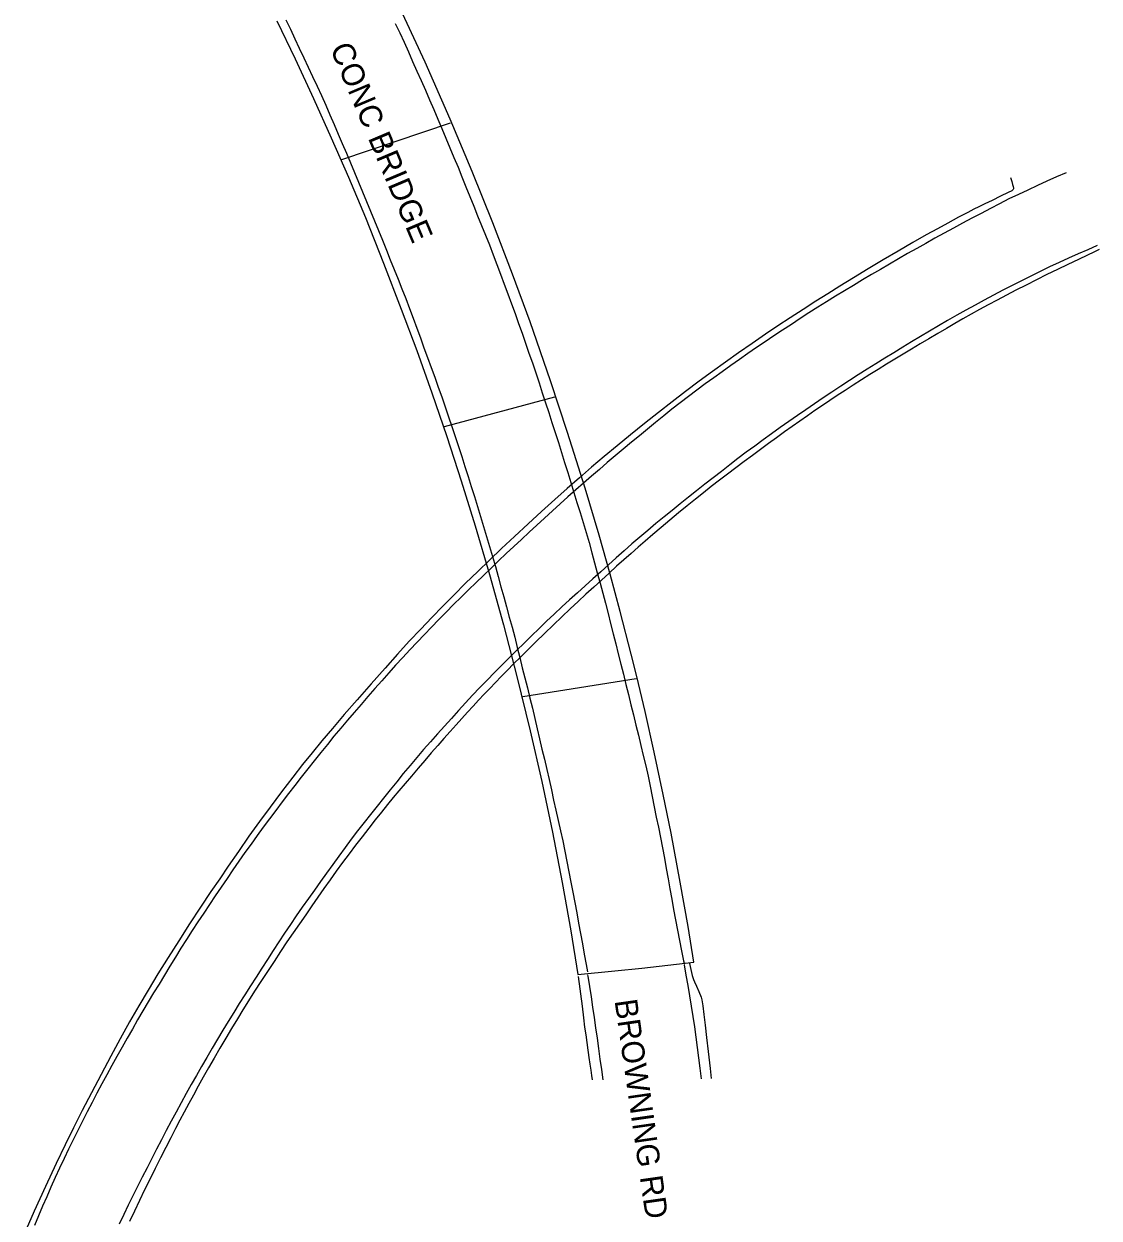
# Model space of a CAD drawing. Extents: x 1948091 to 1975253, y 787267 to 823306.
# Drawn here: x 1967398.7 to 1967655.4, y 801796.8 to 802082 of the extents above; entities that cross this region are included whole.
import ezdxf

# ---------------------------------------------------------------- set-up
doc = ezdxf.new("R2010")
doc.units = 0
for name, color, linetype in [('RD_EX_Bridge', 7, 'Continuous'), ('RD_EX_Bridge_Seam', 7, 'Continuous'), ('RD_EX_Pavement_Markings', 7, 'Continuous'), ('RD_EX_Road', 7, 'Continuous'), ('RD_TX_RoadID', 7, 'Continuous')]:
    doc.layers.add(name, color=color, linetype=linetype)

msp = doc.modelspace()

# ---------------------------------------------------------------- linework, layer by layer
at = {"layer": 'RD_EX_Bridge'}
msp.add_lwpolyline([(1967459.07, 802082.71), (1967463.4, 802073.66), (1967467.78, 802064.2), (1967472.05, 802054.78), (1967476.13, 802045.4), (1967480.19, 802035.73), (1967484.56, 802024.82), (1967488.77, 802013.85), (1967492.47, 802004.03), (1967496.06, 801993.91), (1967499.63, 801983.43), (1967503.05, 801972.84), (1967506.42, 801962.13), (1967509.85, 801950.49), (1967513.15, 801938.46), (1967516.35, 801926.16), (1967519.57, 801913.14), (1967522.31, 801901.06), (1967524.83, 801888.96), (1967527.19, 801876.95), (1967529.26, 801865.43), (1967530.91, 801854.95), (1967539.77, 801855.85), (1967546.2, 801856.46), (1967558.64, 801857.89), (1967557.23, 801866.47), (1967555.37, 801877.04), (1967553.19, 801888.76), (1967551.31, 801897.98), (1967549.17, 801908.09), (1967547, 801917.79), (1967545, 801926.13), (1967543.64, 801931.48), (1967540.99, 801941.68), (1967538.62, 801950.58), (1967535.98, 801959.93), (1967532.63, 801971.14), (1967528.48, 801984.44), (1967524.41, 801996.76), (1967519.52, 802010.8), (1967515.35, 802022.19), (1967510.61, 802034.48), (1967505.67, 802046.75), (1967500.42, 802059.22), (1967494.44, 802072.81), (1967487.47, 802087.95)], dxfattribs=at)
at = {"layer": 'RD_EX_Bridge_Seam'}
for p, q in [((1967474.59, 802049.57), (1967500.52, 802058.35)), ((1967499.07, 801985.84), (1967525.41, 801992.92)), ((1967517.8, 801921.35), (1967544.86, 801925.65))]:
    msp.add_line(p, q, dxfattribs=at)
at = {"layer": 'RD_EX_Pavement_Markings'}
for points in [[(1967461.21, 802082.96), (1967462.28, 802080.7), (1967463.34, 802078.44), (1967464.41, 802076.18), (1967465.48, 802073.91), (1967466.54, 802071.65), (1967467.61, 802069.39), (1967468.68, 802067.13), (1967469.74, 802064.87), (1967470.77, 802062.59), (1967471.74, 802060.29), (1967472.72, 802057.99), (1967473.7, 802055.69), (1967474.68, 802053.39), (1967475.65, 802051.09), (1967476.63, 802048.79), (1967477.61, 802046.49), (1967478.57, 802044.18), (1967479.52, 802041.87), (1967480.47, 802039.55), (1967481.42, 802037.24), (1967482.37, 802034.93), (1967483.31, 802032.62), (1967484.26, 802030.3), (1967485.21, 802027.99), (1967486.14, 802025.67), (1967487.07, 802023.35), (1967488, 802021.03), (1967488.92, 802018.71), (1967489.85, 802016.39), (1967490.73, 802014.05), (1967491.6, 802011.7), (1967492.46, 802009.35), (1967493.32, 802007.01), (1967494.18, 802004.66), (1967495.04, 802002.32), (1967495.91, 801999.97), (1967496.77, 801997.62), (1967497.61, 801995.27), (1967498.42, 801992.91), (1967499.23, 801990.54), (1967500.03, 801988.17), (1967500.84, 801985.81), (1967501.65, 801983.44), (1967502.46, 801981.08), (1967503.22, 801978.7), (1967503.97, 801976.31), (1967504.71, 801973.93), (1967505.46, 801971.54), (1967506.21, 801969.16), (1967506.95, 801966.77), (1967507.68, 801964.38), (1967508.39, 801961.98), (1967509.1, 801959.59), (1967509.81, 801957.19), (1967510.51, 801954.79), (1967511.22, 801952.39), (1967511.91, 801949.99), (1967512.57, 801947.58), (1967513.23, 801945.17), (1967513.88, 801942.76), (1967514.54, 801940.35), (1967515.2, 801937.93), (1967515.85, 801935.52), (1967516.46, 801933.1), (1967517.06, 801930.67), (1967517.66, 801928.25), (1967518.27, 801925.82), (1967518.87, 801923.4), (1967519.47, 801920.97), (1967520.08, 801918.55), (1967520.65, 801916.11), (1967521.22, 801913.68), (1967521.79, 801911.25), (1967522.35, 801908.81), (1967522.92, 801906.38), (1967523.49, 801903.94), (1967524.05, 801901.51), (1967524.59, 801899.07), (1967525.14, 801896.63), (1967525.68, 801894.19), (1967526.22, 801891.75), (1967526.77, 801889.31), (1967527.31, 801886.87), (1967527.81, 801884.42), (1967528.29, 801881.97), (1967528.76, 801879.51), (1967529.23, 801877.06), (1967529.71, 801874.61), (1967530.18, 801872.15), (1967530.65, 801869.7), (1967531.1, 801867.24), (1967531.54, 801864.78), (1967531.99, 801862.32), (1967532.43, 801859.86), (1967532.88, 801857.4), (1967533.21, 801855.59)], [(1967487.32, 802082.1), (1967488.41, 802079.85), (1967489.46, 802077.59), (1967490.47, 802075.3), (1967491.48, 802073.01), (1967492.49, 802070.73), (1967493.5, 802068.44), (1967494.51, 802066.16), (1967495.53, 802063.87), (1967496.52, 802061.58), (1967497.49, 802059.27), (1967498.45, 802056.97), (1967499.42, 802054.66), (1967500.39, 802052.35), (1967501.35, 802050.05), (1967502.32, 802047.74), (1967503.25, 802045.43), (1967504.19, 802043.11), (1967505.12, 802040.79), (1967506.06, 802038.47), (1967507, 802036.15), (1967507.93, 802033.84), (1967508.87, 802031.52), (1967509.8, 802029.2), (1967510.68, 802026.86), (1967511.55, 802024.52), (1967512.43, 802022.18), (1967513.31, 802019.84), (1967514.18, 802017.49), (1967515.06, 802015.15), (1967515.94, 802012.81), (1967516.77, 802010.46), (1967517.59, 802008.1), (1967518.41, 802005.73), (1967519.23, 802003.37), (1967520.06, 802001.01), (1967520.88, 801998.65), (1967521.67, 801996.28), (1967522.44, 801993.9), (1967523.2, 801991.53), (1967523.97, 801989.15), (1967524.74, 801986.77), (1967525.5, 801984.39), (1967526.27, 801982.01), (1967527.03, 801979.63), (1967527.77, 801977.24), (1967528.5, 801974.85), (1967529.24, 801972.46), (1967529.98, 801970.07), (1967530.71, 801967.68), (1967531.45, 801965.3), (1967532.19, 801962.91), (1967532.92, 801960.52), (1967533.63, 801958.12), (1967534.28, 801955.71), (1967534.92, 801953.29), (1967535.56, 801950.88), (1967536.21, 801948.46), (1967536.85, 801946.05), (1967537.49, 801943.63), (1967538.14, 801941.22), (1967538.75, 801938.79), (1967539.36, 801936.37), (1967539.96, 801933.95), (1967540.57, 801931.52), (1967541.18, 801929.1), (1967541.78, 801926.67), (1967542.39, 801924.25), (1967542.99, 801921.82), (1967543.58, 801919.39), (1967544.18, 801916.96), (1967544.77, 801914.54), (1967545.36, 801912.11), (1967545.95, 801909.68), (1967546.55, 801907.25), (1967547.14, 801904.82), (1967547.68, 801902.38), (1967548.17, 801899.93), (1967548.66, 801897.48), (1967549.16, 801895.03), (1967549.65, 801892.58), (1967550.14, 801890.13), (1967550.63, 801887.68), (1967551.12, 801885.23), (1967551.58, 801882.78), (1967552.02, 801880.31), (1967552.47, 801877.86), (1967552.91, 801875.4), (1967553.35, 801872.94), (1967553.79, 801870.48), (1967554.24, 801868.02), (1967554.73, 801865.57), (1967555.21, 801863.11), (1967555.69, 801860.66), (1967556.18, 801858.21), (1967556.28, 801857.72)], [(1967647.46, 802046.45), (1967645.17, 802045.45), (1967642.88, 802044.45), (1967640.62, 802043.38), (1967638.36, 802042.31), (1967636.1, 802041.25), (1967633.84, 802040.17), (1967631.62, 802039.03), (1967629.4, 802037.88), (1967627.17, 802036.74), (1967624.97, 802035.56), (1967622.77, 802034.38), (1967620.57, 802033.19), (1967618.36, 802032.01), (1967616.17, 802030.81), (1967613.99, 802029.58), (1967611.81, 802028.36), (1967609.63, 802027.13), (1967607.46, 802025.91), (1967605.3, 802024.64), (1967603.15, 802023.37), (1967601, 802022.1), (1967598.84, 802020.83), (1967596.7, 802019.55), (1967594.57, 802018.24), (1967592.44, 802016.93), (1967590.31, 802015.63), (1967588.18, 802014.32), (1967586.07, 802012.96), (1967583.98, 802011.6), (1967581.89, 802010.23), (1967579.8, 802008.86), (1967577.71, 802007.48), (1967575.63, 802006.09), (1967573.58, 802004.67), (1967571.53, 802003.24), (1967569.48, 802001.81), (1967567.43, 802000.38), (1967565.4, 801998.93), (1967563.37, 801997.47), (1967561.34, 801996.01), (1967559.34, 801994.51), (1967557.34, 801993.01), (1967555.35, 801991.49), (1967553.37, 801989.96), (1967551.42, 801988.4), (1967549.48, 801986.82), (1967547.55, 801985.24), (1967545.62, 801983.65), (1967543.69, 801982.07), (1967541.77, 801980.46), (1967539.86, 801978.86), (1967537.94, 801977.25), (1967536.05, 801975.61), (1967534.17, 801973.97), (1967532.29, 801972.33), (1967530.41, 801970.68), (1967528.53, 801969.03), (1967526.67, 801967.36), (1967524.83, 801965.67), (1967522.99, 801963.97), (1967521.15, 801962.28), (1967519.32, 801960.59), (1967517.49, 801958.88), (1967515.66, 801957.18), (1967513.83, 801955.48), (1967512.01, 801953.76), (1967510.21, 801952.03), (1967508.41, 801950.29), (1967506.61, 801948.55), (1967504.83, 801946.8), (1967503.04, 801945.05), (1967501.26, 801943.31), (1967499.51, 801941.52), (1967497.75, 801939.74), (1967496, 801937.96), (1967494.28, 801936.15), (1967492.56, 801934.33), (1967490.84, 801932.52), (1967489.13, 801930.69), (1967487.42, 801928.87), (1967485.76, 801927), (1967484.11, 801925.13), (1967482.46, 801923.25), (1967480.82, 801921.37), (1967479.17, 801919.48), (1967477.55, 801917.58), (1967475.93, 801915.68), (1967474.32, 801913.77), (1967472.7, 801911.86), (1967471.13, 801909.92), (1967469.56, 801907.97), (1967467.99, 801906.03), (1967466.44, 801904.07), (1967464.89, 801902.11), (1967463.34, 801900.15), (1967461.82, 801898.17), (1967460.31, 801896.18), (1967458.8, 801894.18), (1967457.3, 801892.18), (1967455.81, 801890.18), (1967454.34, 801888.15), (1967452.89, 801886.12), (1967451.45, 801884.08), (1967450.02, 801882.03), (1967448.59, 801879.97), (1967447.17, 801877.92), (1967445.76, 801875.86), (1967444.36, 801873.79), (1967442.97, 801871.71), (1967441.59, 801869.63), (1967440.22, 801867.54), (1967438.84, 801865.45), (1967437.5, 801863.34), (1967436.16, 801861.23), (1967434.85, 801859.1), (1967433.54, 801856.97), (1967432.23, 801854.85), (1967430.93, 801852.71), (1967429.63, 801850.58), (1967428.33, 801848.44), (1967427.07, 801846.28), (1967425.81, 801844.13), (1967424.57, 801841.96), (1967423.33, 801839.78), (1967422.1, 801837.61), (1967420.87, 801835.43), (1967419.68, 801833.24), (1967418.48, 801831.05), (1967417.28, 801828.85), (1967416.12, 801826.64), (1967414.95, 801824.43), (1967413.78, 801822.22), (1967412.66, 801819.99), (1967411.54, 801817.75), (1967410.43, 801815.51), (1967409.34, 801813.26), (1967408.25, 801811.01), (1967407.2, 801808.75), (1967406.15, 801806.48), (1967405.11, 801804.2), (1967404.12, 801801.91), (1967403.13, 801799.62), (1967402.15, 801797.32), (1967401.19, 801795.01)], [(1967654.93, 802029.09), (1967652.65, 802028.06), (1967650.37, 802027.04), (1967648.09, 802026.01), (1967645.81, 802024.98), (1967643.53, 802023.95), (1967641.28, 802022.87), (1967639.04, 802021.75), (1967636.81, 802020.63), (1967634.59, 802019.49), (1967632.36, 802018.36), (1967630.15, 802017.19), (1967627.95, 802016.01), (1967625.74, 802014.83), (1967623.56, 802013.62), (1967621.37, 802012.41), (1967619.2, 802011.17), (1967617.05, 802009.9), (1967614.89, 802008.63), (1967612.75, 802007.35), (1967610.61, 802006.05), (1967608.48, 802004.76), (1967606.35, 802003.45), (1967604.22, 802002.14), (1967602.09, 802000.83), (1967599.97, 801999.5), (1967597.87, 801998.15), (1967595.76, 801996.81), (1967593.67, 801995.44), (1967591.59, 801994.05), (1967589.51, 801992.66), (1967587.44, 801991.27), (1967585.38, 801989.85), (1967583.33, 801988.43), (1967581.27, 801987.01), (1967579.21, 801985.59), (1967577.19, 801984.12), (1967575.17, 801982.65), (1967573.15, 801981.17), (1967571.13, 801979.7), (1967569.15, 801978.18), (1967567.17, 801976.66), (1967565.18, 801975.13), (1967563.21, 801973.6), (1967561.25, 801972.05), (1967559.28, 801970.51), (1967557.32, 801968.96), (1967555.37, 801967.39), (1967553.43, 801965.82), (1967551.49, 801964.25), (1967549.57, 801962.65), (1967547.65, 801961.04), (1967545.74, 801959.43), (1967543.84, 801957.8), (1967541.97, 801956.15), (1967540.1, 801954.49), (1967538.23, 801952.83), (1967536.37, 801951.16), (1967534.52, 801949.49), (1967532.66, 801947.81), (1967530.8, 801946.14), (1967528.95, 801944.46), (1967527.1, 801942.78), (1967525.29, 801941.06), (1967523.47, 801939.34), (1967521.66, 801937.62), (1967519.87, 801935.87), (1967518.08, 801934.13), (1967516.3, 801932.37), (1967514.53, 801930.61), (1967512.76, 801928.84), (1967511, 801927.07), (1967509.25, 801925.29), (1967507.5, 801923.5), (1967505.79, 801921.67), (1967504.1, 801919.83), (1967502.41, 801917.99), (1967500.74, 801916.14), (1967499.06, 801914.28), (1967497.39, 801912.43), (1967495.74, 801910.55), (1967494.09, 801908.67), (1967492.47, 801906.77), (1967490.85, 801904.86), (1967489.25, 801902.94), (1967487.68, 801901), (1967486.11, 801899.05), (1967484.54, 801897.11), (1967482.98, 801895.15), (1967481.43, 801893.2), (1967479.87, 801891.24), (1967478.34, 801889.27), (1967476.83, 801887.27), (1967475.33, 801885.28), (1967473.85, 801883.26), (1967472.39, 801881.23), (1967470.93, 801879.2), (1967469.47, 801877.17), (1967468.03, 801875.13), (1967466.58, 801873.09), (1967465.13, 801871.06), (1967463.69, 801869.01), (1967462.3, 801866.94), (1967460.9, 801864.86), (1967459.51, 801862.79), (1967458.16, 801860.69), (1967456.8, 801858.59), (1967455.44, 801856.49), (1967454.1, 801854.38), (1967452.76, 801852.27), (1967451.42, 801850.16), (1967450.1, 801848.04), (1967448.78, 801845.91), (1967447.47, 801843.79), (1967446.15, 801841.66), (1967444.89, 801839.51), (1967443.62, 801837.35), (1967442.36, 801835.19), (1967441.1, 801833.03), (1967439.85, 801830.87), (1967438.59, 801828.71), (1967437.38, 801826.53), (1967436.19, 801824.33), (1967435, 801822.13), (1967433.83, 801819.92), (1967432.67, 801817.71), (1967431.5, 801815.5), (1967430.36, 801813.27), (1967429.22, 801811.05), (1967428.08, 801808.83), (1967426.94, 801806.6), (1967425.82, 801804.37), (1967424.71, 801802.13), (1967423.59, 801799.89), (1967422.52, 801797.63), (1967421.45, 801795.37)], [(1967560.42, 801830.1), (1967560.12, 801832.58), (1967559.82, 801835.06), (1967559.49, 801837.53), (1967559.15, 801840.01), (1967558.81, 801842.48), (1967558.47, 801844.96), (1967558.07, 801847.43), (1967557.67, 801849.89), (1967557.25, 801852.35), (1967556.81, 801854.81), (1967556.37, 801857.27), (1967556.34, 801857.39)], [(1967536.94, 801829.84), (1967536.61, 801832.32), (1967536.27, 801834.8), (1967535.92, 801837.27), (1967535.58, 801839.75), (1967535.23, 801842.22), (1967534.89, 801844.7), (1967534.53, 801847.17), (1967534.15, 801849.64), (1967533.77, 801852.11), (1967533.39, 801854.58), (1967533.33, 801854.91)]]:
    msp.add_lwpolyline(points, dxfattribs=at)
at = {"layer": 'RD_EX_Road'}
for points in [[(1967634.2, 802045.27), (1967634.5, 802044.34), (1967634.71, 802043.66), (1967634.84, 802043.15), (1967634.91, 802042.74), (1967634.91, 802042.57), (1967634.84, 802042.41), (1967634.7, 802042.27), (1967634.51, 802042.14), (1967633.62, 802041.69), (1967631.85, 802040.83), (1967629.81, 802039.84), (1967628.11, 802039.02), (1967626.68, 802038.32), (1967625.49, 802037.73), (1967624.02, 802036.97), (1967621.78, 802035.8), (1967619.21, 802034.42), (1967616.75, 802033.08), (1967614.08, 802031.58), (1967610.89, 802029.76), (1967607.38, 802027.74), (1967603.78, 802025.61), (1967600.19, 802023.47), (1967596.73, 802021.37), (1967593.49, 802019.38), (1967590.59, 802017.56), (1967587.75, 802015.75), (1967584.72, 802013.79), (1967581.64, 802011.79), (1967578.69, 802009.86), (1967575.71, 802007.87), (1967572.52, 802005.7), (1967569.28, 802003.45), (1967566.17, 802001.24), (1967563.07, 801998.99), (1967559.87, 801996.63), (1967556.63, 801994.19), (1967553.41, 801991.73), (1967550.15, 801989.2), (1967546.81, 801986.55), (1967543.49, 801983.86), (1967540.28, 801981.22), (1967537.19, 801978.64), (1967534.21, 801976.1), (1967531.3, 801973.58), (1967528.4, 801971.05), (1967525.43, 801968.4), (1967522.27, 801965.56), (1967519.04, 801962.59), (1967515.83, 801959.6), (1967512.73, 801956.68), (1967509.84, 801953.95), (1967507.02, 801951.25), (1967504.12, 801948.42), (1967501.29, 801945.6), (1967498.65, 801942.93), (1967496.07, 801940.26), (1967493.41, 801937.47), (1967490.68, 801934.54), (1967487.88, 801931.49), (1967484.88, 801928.16), (1967481.55, 801924.42), (1967478.2, 801920.59), (1967475.13, 801917.04), (1967472.33, 801913.76), (1967469.8, 801910.75), (1967467.46, 801907.91), (1967465.21, 801905.12), (1967462.86, 801902.11), (1967460.19, 801898.61), (1967457.45, 801894.96), (1967454.9, 801891.48), (1967452.41, 801888), (1967449.87, 801884.37), (1967447.47, 801880.88), (1967445.41, 801877.86), (1967443.33, 801874.77), (1967440.87, 801871.06), (1967438.24, 801867.05), (1967435.63, 801863.03), (1967433.09, 801859.05), (1967430.66, 801855.12), (1967428.34, 801851.27), (1967426.11, 801847.5), (1967423.91, 801843.68), (1967421.68, 801839.65), (1967419.41, 801835.45), (1967417.09, 801831.11), (1967414.8, 801826.74), (1967412.6, 801822.51), (1967410.5, 801818.38), (1967408.5, 801814.34), (1967406.35, 801809.84), (1967403.8, 801804.36), (1967401.14, 801798.49), (1967398.67, 801792.84)], [(1967655.36, 802028.09), (1967655.05, 802027.94), (1967654.12, 802027.51), (1967652.58, 802026.77), (1967650.41, 802025.75), (1967647.93, 802024.56), (1967645.43, 802023.35), (1967642.92, 802022.12), (1967640.39, 802020.86), (1967637.91, 802019.6), (1967635.52, 802018.38), (1967633.23, 802017.19), (1967631.03, 802016.03), (1967628.9, 802014.89), (1967626.83, 802013.76), (1967624.82, 802012.64), (1967622.85, 802011.53), (1967620.89, 802010.4), (1967618.89, 802009.24), (1967616.83, 802008.04), (1967614.73, 802006.8), (1967612.63, 802005.56), (1967610.57, 802004.33), (1967608.56, 802003.12), (1967606.58, 802001.92), (1967604.63, 802000.72), (1967602.65, 801999.49), (1967600.65, 801998.24), (1967598.64, 801996.96), (1967596.64, 801995.69), (1967594.72, 801994.44), (1967592.86, 801993.22), (1967591.07, 801992.03), (1967589.3, 801990.84), (1967587.52, 801989.63), (1967585.73, 801988.39), (1967583.92, 801987.14), (1967582.09, 801985.85), (1967580.23, 801984.53), (1967578.35, 801983.17), (1967576.45, 801981.78), (1967574.53, 801980.35), (1967572.58, 801978.91), (1967570.62, 801977.45), (1967568.64, 801975.97), (1967566.66, 801974.48), (1967564.71, 801973), (1967562.78, 801971.51), (1967560.89, 801970.02), (1967558.97, 801968.5), (1967557, 801966.89), (1967554.96, 801965.21), (1967552.85, 801963.45), (1967550.78, 801961.7), (1967548.83, 801960.04), (1967547, 801958.47), (1967545.3, 801956.99), (1967543.63, 801955.52), (1967541.92, 801954.01), (1967540.17, 801952.45), (1967538.38, 801950.84), (1967536.55, 801949.18), (1967534.71, 801947.5), (1967532.86, 801945.79), (1967531, 801944.06), (1967529.09, 801942.27), (1967527.12, 801940.39), (1967525.07, 801938.44), (1967522.94, 801936.4), (1967520.87, 801934.39), (1967518.95, 801932.51), (1967517.19, 801930.77), (1967515.59, 801929.16), (1967514.09, 801927.63), (1967512.64, 801926.14), (1967511.24, 801924.7), (1967509.88, 801923.29), (1967508.55, 801921.9), (1967507.22, 801920.49), (1967505.89, 801919.06), (1967504.56, 801917.61), (1967503.22, 801916.13), (1967501.83, 801914.59), (1967500.41, 801912.99), (1967498.95, 801911.34), (1967497.46, 801909.64), (1967495.93, 801907.88), (1967494.37, 801906.07), (1967492.77, 801904.22), (1967491.19, 801902.37), (1967489.67, 801900.58), (1967488.22, 801898.87), (1967486.83, 801897.21), (1967485.44, 801895.54), (1967484.01, 801893.77), (1967482.52, 801891.9), (1967480.98, 801889.92), (1967479.41, 801887.89), (1967477.86, 801885.84), (1967476.31, 801883.78), (1967474.77, 801881.7), (1967473.24, 801879.62), (1967471.75, 801877.55), (1967470.28, 801875.48), (1967468.83, 801873.42), (1967467.4, 801871.35), (1967465.94, 801869.25), (1967464.47, 801867.11), (1967462.98, 801864.95), (1967461.47, 801862.74), (1967459.94, 801860.46), (1967458.39, 801858.12), (1967456.81, 801855.71), (1967455.25, 801853.31), (1967453.76, 801850.98), (1967452.33, 801848.73), (1967450.97, 801846.55), (1967449.63, 801844.37), (1967448.26, 801842.11), (1967446.88, 801839.78), (1967445.47, 801837.38), (1967444.09, 801834.98), (1967442.76, 801832.66), (1967441.49, 801830.43), (1967440.29, 801828.28), (1967439.14, 801826.19), (1967438.02, 801824.14), (1967436.94, 801822.14), (1967435.91, 801820.19), (1967434.85, 801818.18), (1967433.73, 801816), (1967432.53, 801813.67), (1967431.26, 801811.18), (1967429.97, 801808.62), (1967428.7, 801806.06), (1967427.46, 801803.52), (1967426.24, 801800.99), (1967425.06, 801798.49), (1967423.92, 801796.03)], [(1967557.55, 801857.64), (1967558.25, 801854.76), (1967558.53, 801853.82), (1967558.76, 801853.22), (1967559.24, 801852.22), (1967559.82, 801850.95), (1967560.33, 801849.57), (1967560.5, 801848.89), (1967560.72, 801847.46), (1967560.97, 801845.46), (1967561.3, 801842.85), (1967561.65, 801839.9), (1967562.01, 801836.6), (1967562.48, 801832.5), (1967562.75, 801830.12)], [(1967531.01, 801854.52), (1967531.93, 801847.4), (1967532.26, 801844.6), (1967532.54, 801842.41), (1967532.8, 801840.54), (1967533.05, 801838.72), (1967533.3, 801836.93), (1967533.38, 801836.32), (1967533.54, 801835.19), (1967533.78, 801833.56), (1967533.99, 801832.12), (1967534.19, 801830.87), (1967534.37, 801829.81)]]:
    msp.add_lwpolyline(points, dxfattribs=at)

# ---------------------------------------------------------------- texts
at = {"layer": 'RD_TX_RoadID'}
for s, rotation, p in [('CONC BRIDGE', 292.9111, (1967471.68, 802076.19)), ('BROWNING RD', 278.1671, (1967539.66, 801848.75))]:
    msp.add_text(s, height=5.4, rotation=rotation, dxfattribs=at).set_placement(p)

doc.saveas('drawing.dxf')
